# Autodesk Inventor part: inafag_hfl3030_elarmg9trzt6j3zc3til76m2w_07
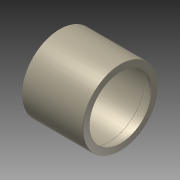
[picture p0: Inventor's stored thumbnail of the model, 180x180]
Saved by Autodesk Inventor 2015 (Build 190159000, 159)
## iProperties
Company: TraceParts S.A.
Created: 2012-12
Part Number: inafag_hfl3030_elarmg9trzt6j3zc3til76m2w_07
Checked By: TraceParts S.A.
Catalog Web Link: www.traceparts.com
Document SubType Name: Modeling
Designer: TraceParts
Material: Generic
Density: 1 g/cm^3
Appearance: Light Beige
Author: TraceParts
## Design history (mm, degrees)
feature "inafag_hfl3030_elarmg9trzt6j3zc3til76m2w"
body "Solid1"
